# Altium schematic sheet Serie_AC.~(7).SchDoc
size A4
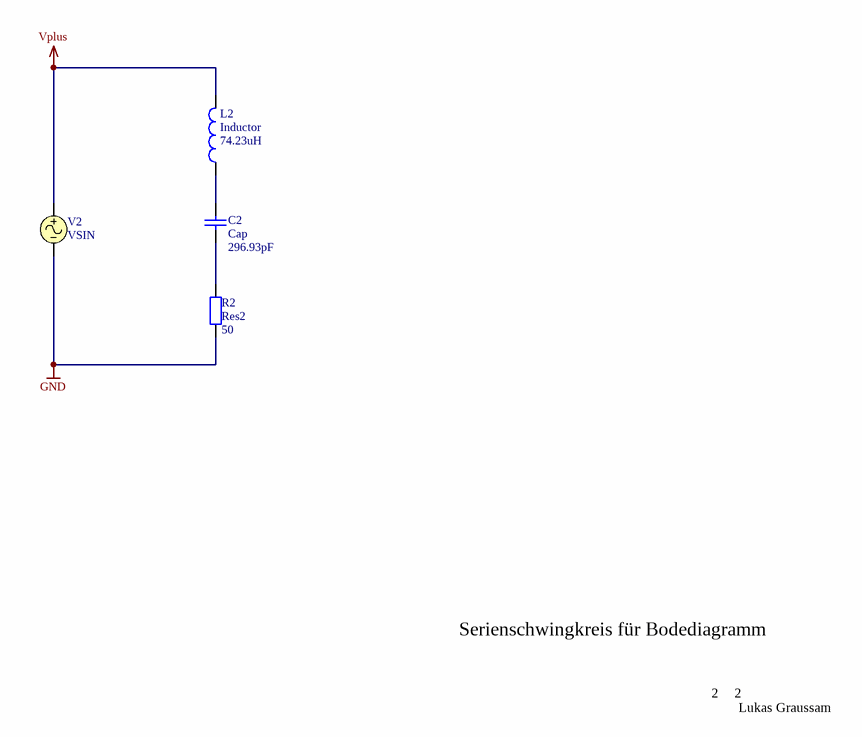
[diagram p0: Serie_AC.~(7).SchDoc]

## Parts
C2  Cap  value 296.93pF  [RAD-0.3]
L2  Inductor  value 74.23uH  [0402-A]
R2  Res2  value 50  [AXIAL-0.4]
V2  VSIN

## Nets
GND: R2.1 V2.2
Vplus: L2.2 V2.1
NetC2_1: C2.1 L2.1
NetC2_2: C2.2 R2.2

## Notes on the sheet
- Serienschwingkreis für Bodediagramm
- 2
- Lukas Graussam

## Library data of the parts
C2 = Cap: Capacitor
L2 = Inductor: Code_IEC: 1005
R2 = Res2: Resistor
V2 = VSIN: Sinusoidal Voltage Source; Note: PCB Footprint - Not required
